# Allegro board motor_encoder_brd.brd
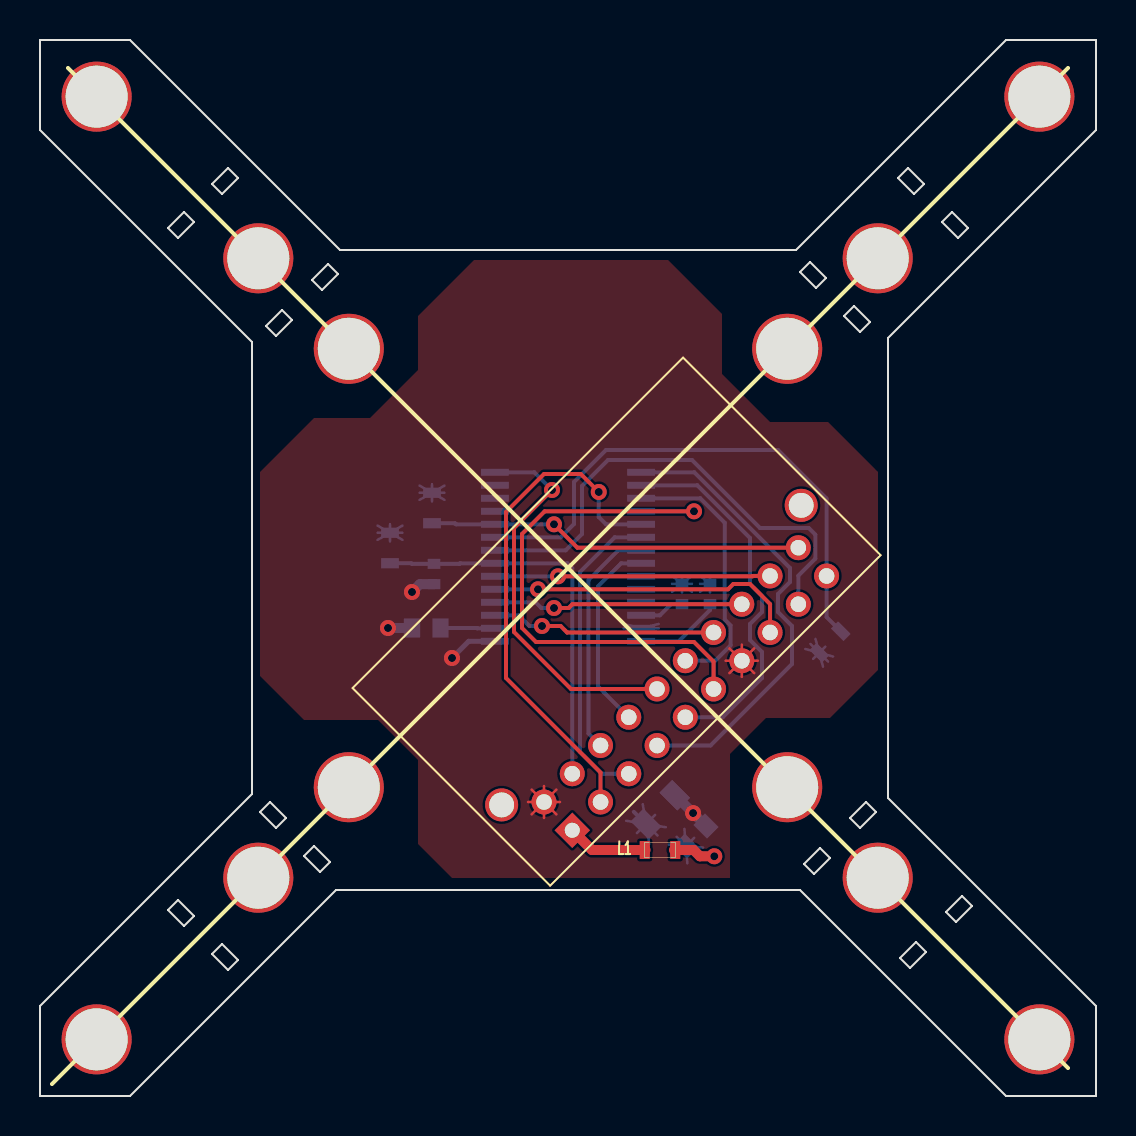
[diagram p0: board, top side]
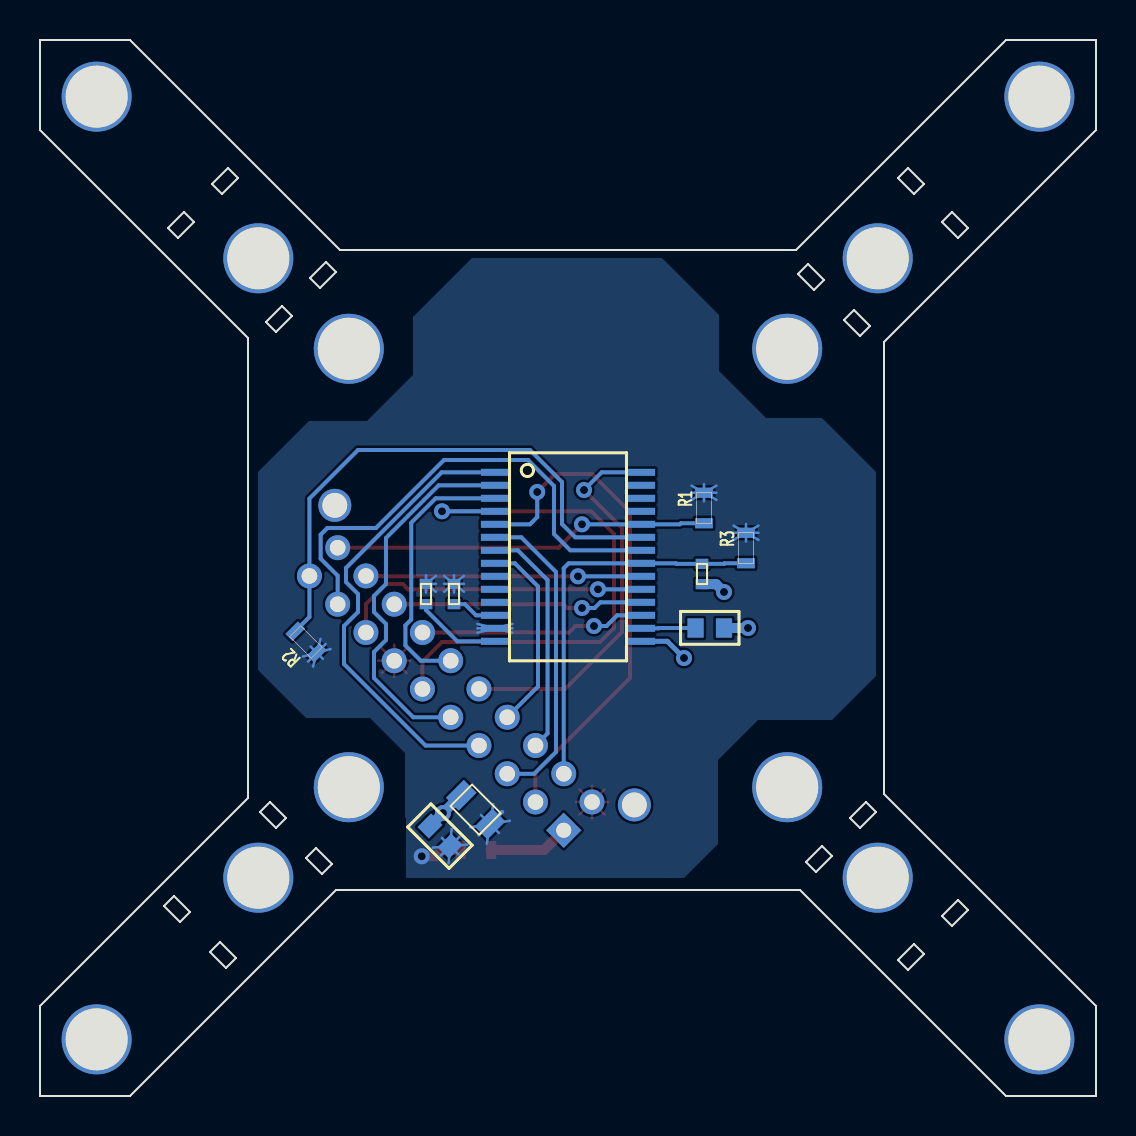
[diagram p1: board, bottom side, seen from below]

Outline 52.8 x 52.8 mm; copper layers: TOP, BOTTOM. Coordinates in mm from the lower left corner of the outline.
Outline path: 0,52.8 0,48.3 ; 0,52.8 0,48.3 ; 0,52.8 4.5,52.8 ; 0,52.8 4.5,52.8 ; 0,48.3 10.6,37.7 ; 0,48.3 10.6,37.7 ; 10.6,37.7 10.6,15.1 ; 10.6,37.7 10.6,15.1 ; 0,4.5 0,0 ; 0,4.5 0,0 ; 0,4.5 10.6,15.1 ; 0,4.5 10.6,15.1 ; 0,0 4.5,0 ; 0,0 4.5,0 ; 4.5,0 14.8,10.3 ; 4.5,0 14.8,10.3 ; 4.5,52.8 15,42.3 ; 4.5,52.8 15,42.3 ; 14.8,10.3 38,10.3 ; 14.8,10.3 38,10.3 ; 38,10.3 48.3,0 ; 38,10.3 48.3,0 ; 15,42.3 37.8,42.3 ; 15,42.3 37.8,42.3 ; 37.8,42.3 48.3,52.8 ; 37.8,42.3 48.3,52.8 ; 48.3,0 52.8,0 ; 48.3,0 52.8,0 ; 42.4,37.9 52.8,48.3 ; 42.4,37.9 52.8,48.3 ; 42.4,37.9 42.4,14.9 ; 42.4,37.9 42.4,14.9 ; 52.8,48.3 52.8,52.8 ; 52.8,48.3 52.8,52.8 ; 42.4,14.9 52.8,4.5 ; 42.4,14.9 52.8,4.5 ; 48.3,52.8 52.8,52.8 ; 48.3,52.8 52.8,52.8 ; 52.8,0 52.8,4.5 ; 52.8,0 52.8,4.5 ; 6.4,43.4 7.2,44.2 7.7,43.7 6.9,42.9 6.4,43.4 ; 6.4,9.3 6.9,9.8 7.7,9 7.2,8.5 6.4,9.3 ; 8.6,45.6 9.4,46.4 9.9,45.9 9.1,45.1 8.6,45.6 ; 8.6,7.1 9.1,7.6 9.9,6.8 9.4,6.3 8.6,7.1 ; 11,14.2 11.5,14.7 12.3,13.9 11.8,13.4 11,14.2 ; 11.3,38.5 12.1,39.3 12.6,38.8 11.8,38 11.3,38.5 ; 13.2,12 13.7,12.5 14.5,11.7 14,11.2 13.2,12 ; 13.6,40.8 14.4,41.6 14.9,41.1 14.1,40.3 13.6,40.8 ; 38,41.2 38.5,41.7 39.3,40.9 38.8,40.4 38,41.2 ; 38.2,11.6 39,12.4 39.5,11.9 38.7,11.1 38.2,11.6 ; 40.2,39 40.7,39.5 41.5,38.7 41,38.2 40.2,39 ; 40.5,13.9 41.3,14.7 41.8,14.2 41,13.4 40.5,13.9 ; 42.9,45.9 43.4,46.4 44.2,45.6 43.7,45.1 42.9,45.9 ; 43,6.9 43.8,7.7 44.3,7.2 43.5,6.4 43,6.9 ; 45.1,43.7 45.6,44.2 46.4,43.4 45.9,42.9 45.1,43.7 ; 45.3,9.2 46.1,10 46.6,9.5 45.8,8.7 45.3,9.2

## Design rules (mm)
constraint set DEFAULT: min track width 0.127
net group DP_A: nets A W/NCOS
net group DP_B: nets B RI

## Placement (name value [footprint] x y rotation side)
BR1  CIRCUIT BREAKER  [CAP0402]  19.7 26.1 90 bottom
BR2  CIRCUIT BREAKER  [CAP0402]  32.1 25.1 270 bottom
BR3  CIRCUIT BREAKER  [CAP0402]  33.5 25.1 270 bottom
C1  100n  [SMC0603]  18.6 23.4 0 bottom
C2  100n  [SMC0603]  33.3 13.5 225 bottom
C3  10u  [CAP0805]  30.3 13.6 45 bottom
J1  S20B-PADSS-1(LF)(SN)  [JST_PADSS_90DEG_10X2]  25.2 14.7 45 top
L1  BLM18PG300SN1D  [RES0603]  31 12.3 180 top
NOREF  -  [unnamed]  41.89 10.91 0 top
NOREF#2  -  [unnamed]  15.44 15.44 0 top
NOREF#3  -  [unnamed]  49.97 2.83 0 top
NOREF#4  -  [#2]  15.44 15.44 90 top
NOREF#5  -  [#2]  2.83 49.97 0 top
NOREF#6  -  [unnamed]  2.83 49.97 0 top
NOREF#7  -  [#2]  52.8 0 90 top
NOREF#8  -  [unnamed]  41.89 41.89 0 top
NOREF#9  -  [#2]  0 52.8 0 top
NOREF#10  -  [#2]  38 10.3 90 top
NOREF#11  -  [unnamed]  2.83 2.83 0 top
NOREF#12  -  [unnamed]  10.91 41.89 0 top
NOREF#13  -  [#2]  2.83 2.83 90 top
NOREF#14  -  [unnamed]  10.91 10.91 0 top
NOREF#15  -  [#2]  2.83 2.83 0 top
NOREF#16  -  [#2]  10.91 10.91 90 top
NOREF#17  -  [#2]  15.44 15.44 0 top
NOREF#18  -  [#2]  10.91 10.91 0 top
NOREF#19  -  [unnamed]  37.36 15.44 0 top
NOREF#20  -  [#2]  53.09 46.37 0 top
NOREF#21  -  [unnamed]  15.44 37.36 0 top
NOREF#22  -  [unnamed]  49.97 49.97 0 top
NOREF#23  -  [unnamed]  37.36 37.36 0 top
NOREF#24  -  [#2]  41.04 31.48 0 top
NOREF#25  -  [#2]  44.9 38.12 0 top
R1  51k  [RES0603]  19.6 29.4 90 bottom
R2  51k  [RES0603]  39.5 22.7 225 bottom
R3  51k  [RES0603]  17.5 27.4 90 bottom
U1  AM4096  [SSOP28-LD]  26.4 26.96 270 bottom

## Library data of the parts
BR1-BR3 = CIRCUIT BREAKER_0
C1 = C: signal model: DEFAULT_CAPACITOR_100000pF_2_1
C2 = C: signal model: capacitor20pF
C3 = C_elect_0: signal model: DEFAULT_CAPACITOR_1e+07pF_2_1
J1 = HEADER 10X2
L1 = CHOKE HASH-IRON: signal model: cable_espice
R1-R3 = R: signal model: DEFAULT_RESISTOR_51000OHM_2_1
U1 = AM4096: signal model: CDS_lvds_device

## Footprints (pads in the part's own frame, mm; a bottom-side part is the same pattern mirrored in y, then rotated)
CAP0402
  rect 0.508x0.635 smd: 1(-0.508,0) 2(0.508,0)
CAP0805
  rect 0.914x1.27 smd: 1(0,0) 2(2.032,0)
JST_PADSS_90DEG_10X2
  round 1.65 hole 1.245: (-1.6,1.395) (19.582,1.395)
  rect 1.25x1.25 hole 0.75: 1(0,-2)
  round 1.25 hole 0.78: 2(0,0) 3(1.998,-2) 4(1.998,0) 5(3.996,-2) 6(3.996,0) 7(5.994,-2) 8(5.994,0) 9(7.992,-2) 10(7.992,0) 11(9.99,-2) 12(9.99,0) 13(11.988,-2) 14(11.988,0) 15(13.986,-2) 16(13.986,0) 17(15.984,-2) 18(15.984,0) 19(17.982,-2) 20(17.982,0)
RES0603
  rect 0.508x0.889 smd: 1(-0.762,0) 2(0.762,0)
SMC0603
  rect 0.813x0.965 smd: 1(0,0) 2(1.422,0)
SSOP28-LD
  rect 0.348x1.397 smd: 1(-4.225,-3.656) 2(-3.575,-3.656) 3(-2.925,-3.656) 4(-2.275,-3.656) 5(-1.625,-3.656) 6(-0.975,-3.656) 7(-0.325,-3.656) 8(0.325,-3.656) 9(0.975,-3.656) 10(1.625,-3.656) 11(2.275,-3.656) 12(2.925,-3.656) 13(3.575,-3.656) 14(4.225,-3.656) 15(4.225,3.656) 16(3.575,3.656) 17(2.925,3.656) 18(2.275,3.656) 19(1.625,3.656) 20(0.975,3.656) 21(0.325,3.656) 22(-0.325,3.656) 23(-0.975,3.656) 24(-1.625,3.656) 25(-2.275,3.656) 26(-2.925,3.656) 27(-3.575,3.656) 28(-4.225,3.656)
unnamed
  round 3.502 hole 3.1: 1(0,0)

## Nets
VIN: J1.1 L1.2
0: BR1.1 C1.1 C2.1 C3.2(-) J1.2 J1.13 U1.15
A: J1.11 U1.4
B: J1.12 U1.3
CLOCK: J1.10 U1.28
DATA: J1.7 U1.1
MAG: J1.14 U1.17
PSM: BR1.2 J1.4 R3.1 U1.21
REFN: J1.16 U1.18
REFP: J1.15 U1.19
RI: J1.9 U1.2
SCL: J1.20 R1.1 U1.24
SDA: J1.19 R2.1 U1.23
TD/PCOS: J1.8 U1.8
U/NSIN: J1.6 U1.7
V/PSIN: J1.5 U1.6
VEXT: BR2.1 BR3.1 C2.2 C3.1 L1.1 R1.2 R2.2 R3.2 U1.13
VOUT/TOUT: J1.18 U1.20
W/NCOS: J1.3 U1.5
ZERO: J1.17 U1.22(ZERO)
N01073: C1.2 U1.16
N03135: BR2.2 U1.12
N03141: BR3.2 U1.14

Pads without a net: NOREF 1; NOREF#2 1; NOREF#3 1; NOREF#6 1; NOREF#8 1; NOREF#11 1; NOREF#12 1; NOREF#14 1; NOREF#19 1; NOREF#21 1; NOREF#22 1; NOREF#23 1; U1 9 10 11 25 26 27

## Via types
v1: diameter 0.8, hole 0.4, TOP to BOTTOM, 13 vias

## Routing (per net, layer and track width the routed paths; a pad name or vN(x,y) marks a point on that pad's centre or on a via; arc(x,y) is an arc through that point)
VIN: length 4.1
  TOP w0.5: J1.1 27.6,12.3 L1.2 30.28,12.3
0: length 20.6
  TOP w0.127: 24.58,15.32 J1.2 ; J1.2 26,14.7 ; J1.2 24.58,14.08 ; J1.2 25.2,13.9 ; J1.2 25.82,14.08 ; J1.2 25.2,15.5 ; J1.2 25.82,15.32 ; J1.2 24.4,14.7 ; J1.13 35.71,21.14 ; J1.13 34.47,21.14 ; J1.13 35.89,21.76 ; J1.13 34.47,22.38 ; J1.13 35.09,22.57 ; J1.13 34.29,21.76 ; J1.13 35.71,22.38 ; J1.13 35.09,20.96
  BOTTOM w0.25: U1.15 21.43,22.73 v1(20.6,21.9)
  BOTTOM w0.5: C2.1 v1(32.65,14.15) 32.1,14.7 32.07,14.7 C3.2 ; v1(18.6,25.2) 18.99,25.59 BR1.1 ; C1.1 v1(17.4,23.4)
A: length 28.1
  TOP w0.2: v1(32.7,29.23) 25.23,29.23 24.1,28.1 24.1,23.4 24.8,22.7 32.7,22.7 33.68,21.72 J1.11
  BOTTOM w0.2: U1.4 v1(32.7,29.23)
B: length 13.5
  BOTTOM w0.2: J1.12 33.76,21.76 34.53,22.53 34.53,23.53 34.24,23.82 34.24,28.66 33.02,29.88 30.06,29.88
CLOCK: length 19.4
  TOP w0.2: v1(25.6,30.3) 23.7,28.4 23.7,23.2 26.55,20.35 J1.10
  BOTTOM w0.2: v1(25.6,30.3) 24.71,31.18 U1.28
DATA: length 23.2
  BOTTOM w0.2: J1.7 33.52,17.52 37.6,21.6 37.6,23.5 36.9,24.2 36.9,25.1 37.5,25.7 37.5,26.4 32.71,31.18 U1.1
MAG: length 11.3
  TOP w0.2: v1(25.1,23.5) 26.03,23.5 26.35,23.18 J1.14
  BOTTOM w0.2: v1(25.1,23.5) 24.47,23.5 23.94,24.03 U1.17
PSM: length 19.5
  BOTTOM w0.2: J1.4 26.61,26.39 26.36,26.63 21,26.63 20.97,26.61 BR1.2 18.6,26.61 18.57,26.64 R3.1
REFN: length 12.5
  TOP w0.2: v1(25.7,24.4) 26.43,24.4 26.62,24.59 J1.16
  BOTTOM w0.2: v1(25.7,24.4) 25.07,24.4 24.78,24.68 U1.18
REFP: length 15.7
  TOP w0.2: J1.15 36.5,24.6 35.5,25.6 34.66,25.6 34.4,25.33 v1(24.9,25.33)
  BOTTOM w0.2: 22.74,25.33 v1(24.9,25.33)
RI: length 18.9
  BOTTOM w0.2: U1.2 32.86,30.53 35.5,27.9 35.5,25.6 36.1,25 36.1,24.2 35.5,23.6 35.5,22.8 36.1,22.2 36.1,20.9 34.14,18.94 J1.9
SCL: length 18.8
  TOP w0.2: v1(25.7,28.58) 26.87,27.42 J1.20
  BOTTOM w0.2: R1.1 20.75,28.64 20.8,28.58 U1.24 v1(25.7,28.58)
SDA: length 27.6
  BOTTOM w0.2: R2.1 39.33,23.95 J1.19 39.33,29.87 36.9,32.3 28.3,32.3 26.7,30.7 26.7,28.6 26.04,27.93 U1.23
TD/PCOS: length 9.8
  BOTTOM w0.2: J1.8 27.9,20.48 27.9,25.48 29.06,26.63 U1.8
U/NSIN: length 11.8
  BOTTOM w0.2: J1.6 27.42,18.13 27.42,25.8 28.91,27.29 30.06,27.29
V/PSIN: length 15.7
  BOTTOM w0.2: U1.6 28.73,27.93 27,26.2 27,17.2 28.09,16.11 J1.5
VEXT: length 42.4
  TOP w0.5: v1(33.71,11.99) 33,11.99 32.68,12.3 L1.1 31.7,12.3
  BOTTOM w0.127: R2.2 39.4,21.72 ; R2.2 38.77,22.85 ; R2.2 39.15,21.47 ; R2.2 38.52,22.6 ; R2.2 39.27,22.47 ; R2.2 38.66,21.86 ; R2.2 39.65,21.97 ; R2.2 38.27,22.35 ; R1.2 20.22,29.81 ; R1.2 18.98,30.52 ; R1.2 20.22,30.52 ; R1.2 18.98,29.81 ; R1.2 19.6,29.73 ; R1.2 19.6,30.59 ; R1.2 20.22,30.16 ; R1.2 18.98,30.16 ; 17.5,27.73 R3.2 ; R3.2 18.12,27.81 ; R3.2 16.88,28.52 ; R3.2 16.88,28.16 ; R3.2 17.5,28.59 ; R3.2 16.88,27.81 ; R3.2 18.12,28.52 ; R3.2 18.12,28.16 ; C2.2 32.71,12.91 ; C2.2 31.83,12.96 ; C2.2 31.88,12.08 ; C2.2 32.22,13.35 ; C2.2 31.43,12.57 ; C2.2 32.76,12.03 ; C2.2 33.15,12.42 ; C2.2 32.37,11.63 ; 29.85,13.15 C3.1 ; C3.1 30.46,12.61 ; C3.1 30.14,14.59 ; C3.1 31.29,13.44 ; C3.1 29.31,13.76 ; C3.1 30.87,13.03 ; C3.1 30.75,14.05 ; 33,26 BR3.1 ; BR3.1 33,25.21 ; BR3.1 33.5,26.04 ; BR3.1 33,25.61 ; BR3.1 33.5,25.18 ; 31.6,25.21 BR2.1 ; BR2.1 31.6,26 ; BR2.1 32.6,25.61 ; BR2.1 32.1,25.18 ; BR2.1 32.6,26 ; BR2.1 32.6,25.21 ; BR2.1 32.1,26.04 ; BR2.1 31.6,25.61 ; 29.18,23.17 30.06,23.38 ; 30.06,23.38 29.18,23.6 ; 30.06,23.38 30.93,23.17 ; 30.06,23.38 30.93,23.38 ; 30.06,23.38 30.93,23.6 ; 30.06,23.38 29.18,23.38
  BOTTOM w0.2: 29.69,14.21 C3.1
VOUT/TOUT: length 13.8
  TOP w0.2: v1(25.9,25.98) 35.63,25.98 35.65,26 J1.18
  BOTTOM w0.2: U1.20 v1(25.9,25.98)
W/NCOS: length 25.8
  TOP w0.2: v1(27.94,30.2) 27.04,31.1 25.2,31.1 23.3,29.2 23.3,20.9 28.03,16.17 J1.3
  BOTTOM w0.2: 30.06,28.58 28.3,28.58 27.94,28.95 v1(27.94,30.2)
ZERO: length 24.7
  BOTTOM w0.2: U1.22 26.29,27.29 27.1,28.1 27.1,30.5 28.4,31.8 32.6,31.8 36,28.4 38.43,28.4 38.77,28.07 38.77,26.87 37.92,26.02 J1.17
N01073: length 2.7
  BOTTOM w0.2: C1.2 21.85,23.4 21.85,23.38 U1.16
N03135: length 2.3
  BOTTOM w0.2: U1.12 31,24.03 31.56,24.59 BR2.2
N03141: length 4.4
  BOTTOM w0.2: BR3.2 33.5,24.3 31.93,22.73 U1.14

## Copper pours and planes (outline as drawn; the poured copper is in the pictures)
0 on TOP: 11,31.2 11,21 13.2,18.8 16.9,18.8 18.9,16.8 18.9,12.6 20.6,10.9 34.5,10.9 34.5,17.1 36.3,18.9 39.5,18.9 41.9,21.3 41.9,31.2 39.4,33.7 36.5,33.7 34.1,36.1 34.1,39.1 31.4,41.8 21.7,41.8 18.9,39 18.9,36.3 16.5,33.9 13.7,33.9 ; 2 cut-outs
VEXT on BOTTOM: 11,31.2 11,21 13.2,18.8 16.9,18.8 18.9,16.8 18.9,12.6 20.6,10.9 34.5,10.9 34.5,13.9 34.55,13.95 34.55,17.15 36.3,18.9 39.5,18.9 41.9,21.3 41.9,31.2 39.35,33.75 36.45,33.75 34.15,36.05 34.15,38.95 31.2,41.9 21.7,41.9 18.85,39.05 18.85,36.25 16.5,33.9 13.7,33.9 ; 12 cut-outs
